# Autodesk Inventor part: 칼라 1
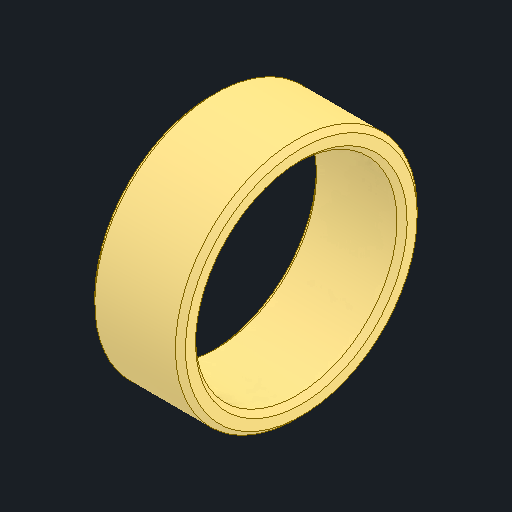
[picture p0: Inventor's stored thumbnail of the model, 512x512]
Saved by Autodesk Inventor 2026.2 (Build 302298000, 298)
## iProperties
Created: 2025-11
Part Number: 칼라 1
Material: 강철, 연강
Document SubType Name: Modeling
Designer: PC2-07
Density: 7.85 g/cm^3
Appearance: 기본값
Author: jhkim
Sending System: Autodesk Inventor 2026
Preprocessor: ST-DEVELOPER v20.1
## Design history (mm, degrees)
feature "솔리드1"
node "솔리드2"
